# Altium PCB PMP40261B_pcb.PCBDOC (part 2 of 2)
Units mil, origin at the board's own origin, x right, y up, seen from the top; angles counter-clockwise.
Board outline 16142.73 x 9056.12 mil, 2 copper layers (TOP, BOTTOM), stack 10.4 mil thick; 242 components, 121 nets, 575 pads, 103 vias.
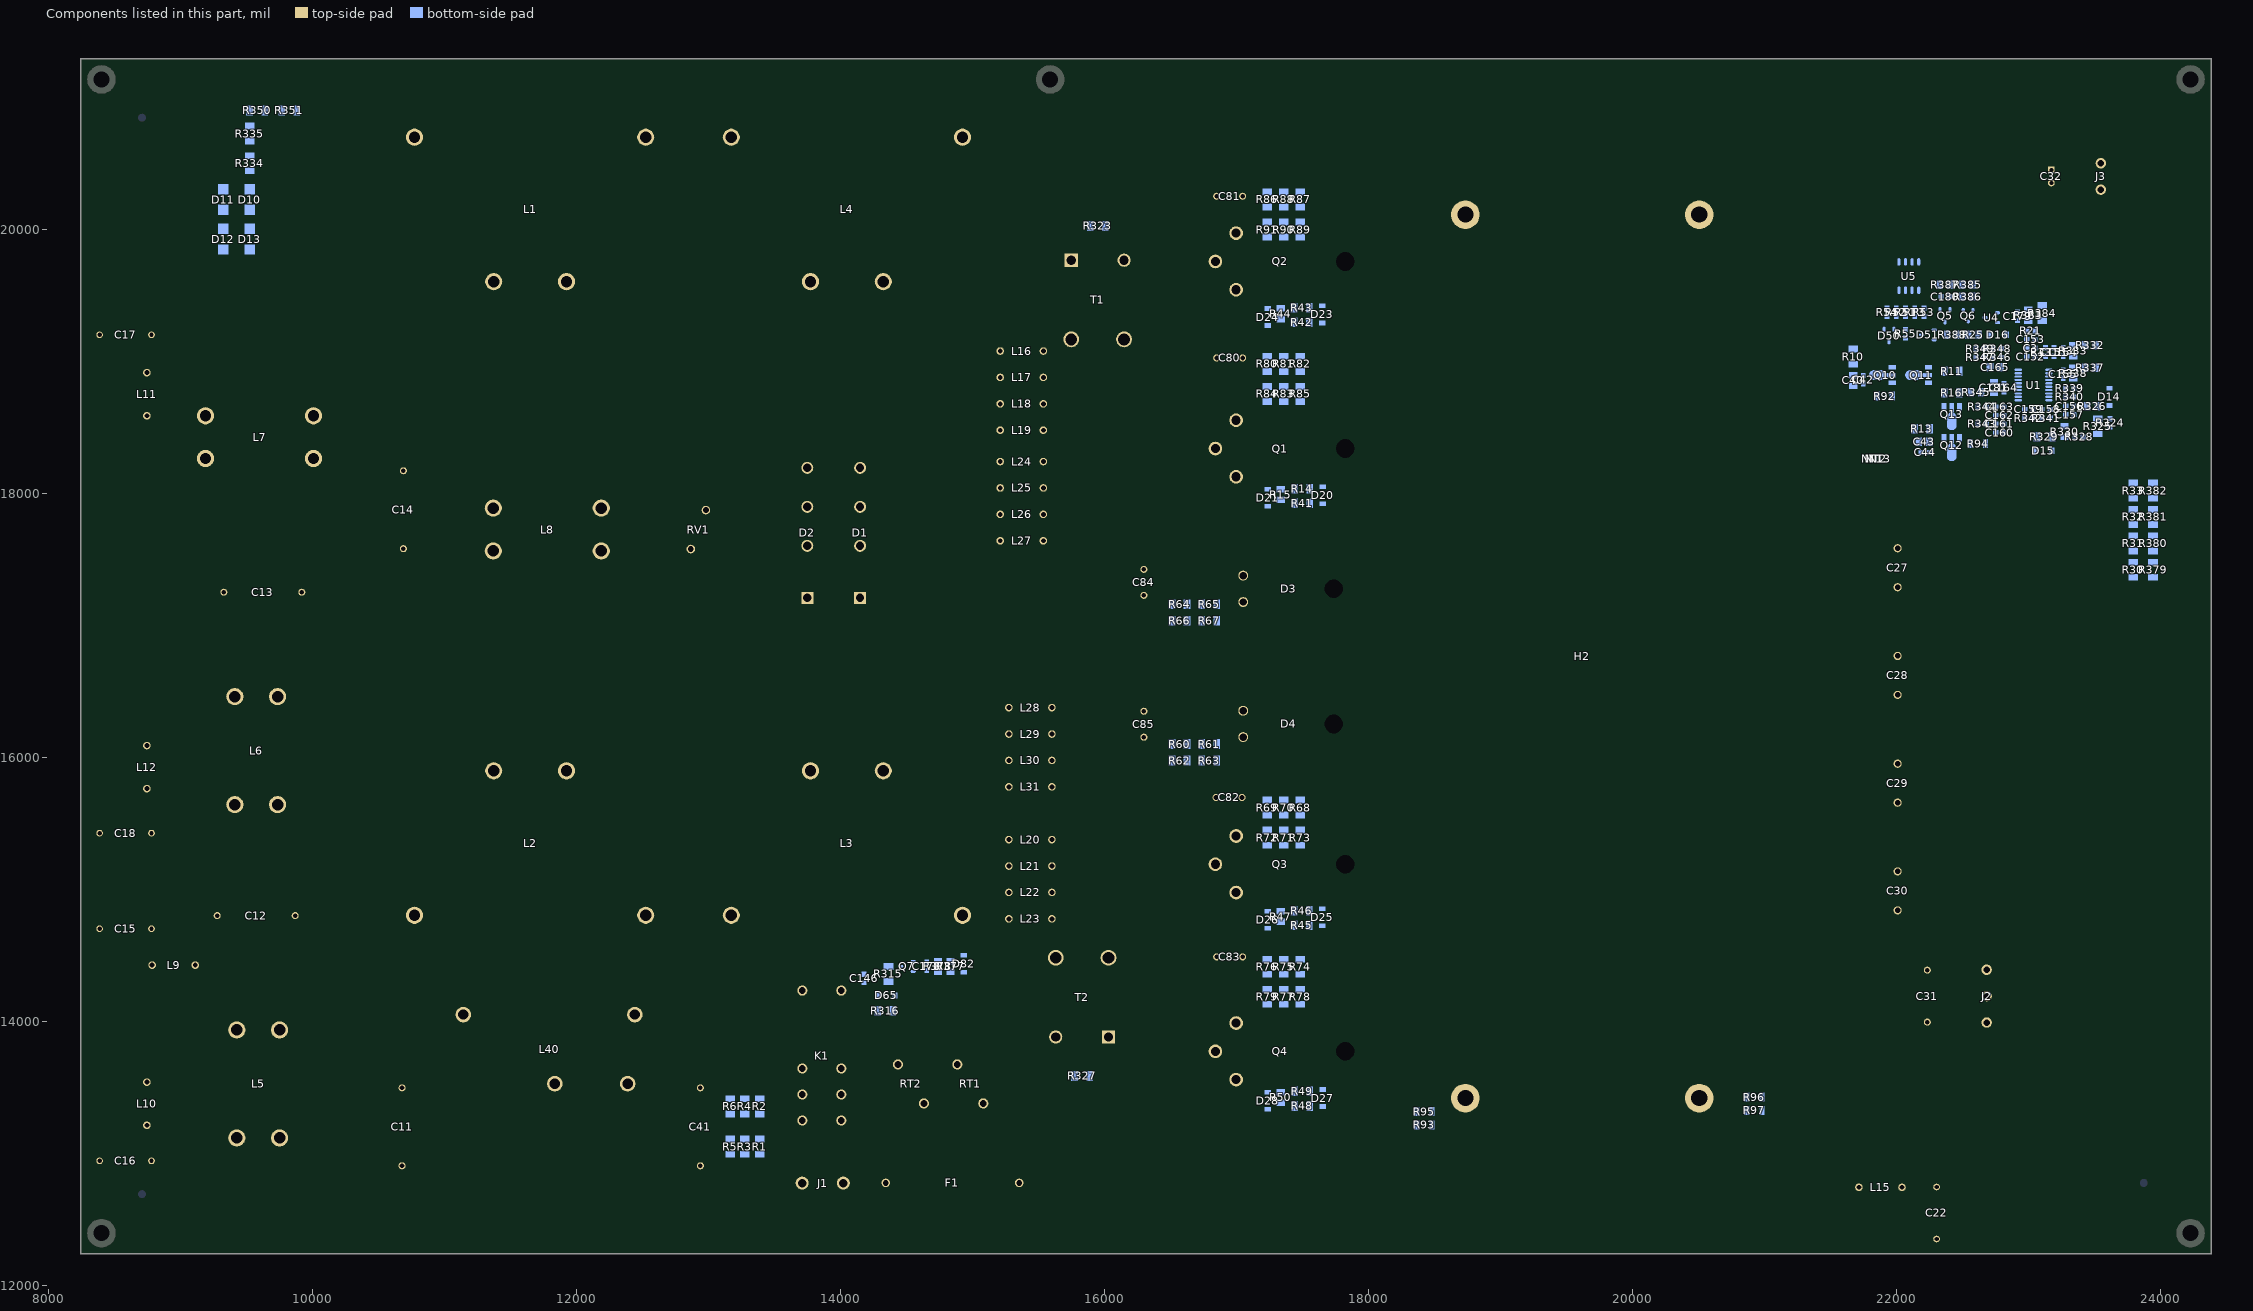
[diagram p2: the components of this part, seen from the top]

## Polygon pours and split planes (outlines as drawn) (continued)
NETR80_2 on BOTTOM "BOTTOM-NETR80_2" (solid, pour order 1054): 17515,18790 17190,18790 17170,18810 17170,18940 17180,18950 17525,18950 17540,18935 17540,18815 17515,18790
NETR74_2 on BOTTOM "BOTTOM-NETR74_2" (solid, pour order 1055): 17515,14223.07 17190,14223.07 17170,14243.07 17170,14373.07 17180,14383.07 17525,14383.07 17540,14368.07 17540,14248.07 17515,14223.07
NETR68_2 on BOTTOM "BOTTOM-NETR68_2" (solid, pour order 1056): 17535,15428.07 17205,15428.07 17190,15443.07 17190,15573.07 17195,15578.07 17535,15578.07 17545,15568.07 17545,15438.07 17535,15428.07
NETR64_1 on BOTTOM "BOTTOM-NETR64_1" (solid, pour order 1057): 16745,16990 16620,16990 16600,17010 16600,17190 16630,17220 16740,17220 16765,17195 16765,17005 16750,16990 16745,16990
NETR60_1 on BOTTOM "BOTTOM-NETR60_1" (solid, pour order 1058): 16745,15930 16620,15930 16600,15950 16600,16130 16630,16160 16740,16160 16765,16135 16765,15945 16750,15930 16745,15930
NETR1_1 on BOTTOM "BOTTOM-NETR1_1" (solid, pour order 1059): 13430,13095 13150,13095 13125,13120 13125,13300 13137.5,13312.5 13437.5,13312.5 13450,13300 13450,13115 13430,13095
NETL20_1 on BOTTOM "BOTTOM-NETL20_1" (solid, pour order 1060): 15550,14425 15525,14450 15525,15350 15525,15440 15560,15475 15715,15475 15725,15475 15795,15475 15825,15445 15825,14460 15790,14425 15735,14425 15550,14425
NETL16_1 on BOTTOM "BOTTOM-NETL16_1" (solid, pour order 1061): 15750,18425 15500,18425 15450,18475 15450,19200 15475,19225 15800,19225 15825,19200 15825,18500 15750,18425
NETL4_2 on BOTTOM "BOTTOM-NETL4_2" (solid, pour order 1062): 17 vertices, not listed, extent 14225,17575 15300,19700
NETL3_1 on BOTTOM "BOTTOM-NETL3_1" (solid, pour order 1063): 20 vertices, not listed, extent 14225,14600 15375,16475
NETL2_1 on BOTTOM "BOTTOM-NETL2_1" (solid, pour order 1064): 11825,15825 11825,15975 11825,16050 11900,16125 13825,16125 13900,16050 13900,15950 13900,15825 13900,15700 13850,15650 11900,15650 11825,15725 11825,15825
NETL1_2 on BOTTOM "BOTTOM-NETL1_2" (solid, pour order 1065): 18 vertices, not listed, extent 11825,19425 13900,20025
NETF1_2 on BOTTOM "BOTTOM-NETF1_2" (solid, pour order 1066): 13950,12700 13950,12825 13950,12875 14000,12925 14375,12925 14425,12875 14425,12825 14425,12700 14425,12650 14375,12600 14000,12600 13950,12650 13950,12700
NETF1_1 on BOTTOM "BOTTOM-NETF1_1" (solid, pour order 1067): 19 vertices, not listed, extent 13650,12675 15500,13425
NETD1_2 on BOTTOM "BOTTOM-NETD1_2" (solid, pour order 1068): 27 vertices, not listed, extent 11100,15625 14225,17650
NETC85_2 on BOTTOM "BOTTOM-NETC85_2" (solid, pour order 1069): 16245,16175 16475,16175 16535,16115 16535,15935 16525,15925 16425,15925 16395,15955 16395,16015 16365,16045 16250,16045 16230,16065 16230,16160 16245,16175
NETC85_1 on BOTTOM "BOTTOM-NETC85_1" (solid, pour order 1070): 22 vertices, not listed, extent 15525,15675 17100,16455
NETC84_2 on BOTTOM "BOTTOM-NETC84_2" (solid, pour order 1071): 16250,17245 16480,17245 16540,17185 16540,17005 16530,16995 16430,16995 16400,17025 16400,17085 16370,17115 16255,17115 16235,17135 16235,17230 16250,17245
NETC84_1 on BOTTOM "BOTTOM-NETC84_1" (solid, pour order 1072): 23 vertices, not listed, extent 15450,17347.5 17100,18300
NETC83_2 on BOTTOM "BOTTOM-NETC83_2" (solid, pour order 1073): 17420,14448.07 17115,14448.07 17090,14423.07 17045,14423.07 17025,14443.07 17025,14538.07 17075,14588.07 17500,14588.07 17525,14588.07 17545,14568.07 17545,14548.07 17545,14463.07 17530,14448.07 17420,14448.07
NETC82_2 on BOTTOM "BOTTOM-NETC82_2" (solid, pour order 1074): 17540,15658.07 17143.07,15658.07 17040,15658.07 17020,15678.07 17020,15743.07 17075,15798.07 17540,15798.07 17550,15788.07 17550,15668.07 17540,15658.07
NETC81_2 on BOTTOM "BOTTOM-NETC81_2" (solid, pour order 1075): 17540,20265 17120,20265 17075,20220 17040,20220 17020,20240 17020,20350 17075,20405 17540,20405 17550,20395 17550,20275 17540,20265
NETC80_2 on BOTTOM "BOTTOM-NETC80_2" (solid, pour order 1076): 17420,19015 17115,19015 17090,18990 17045,18990 17025,19010 17025,19105 17075,19155 17500,19155 17525,19155 17545,19135 17545,19115 17545,19030 17530,19015 17420,19015
NETC80_1 on BOTTOM "BOTTOM-NETC80_1" (solid, pour order 1077): 45 vertices, not listed, extent 16075,18235 16895,20285
NETC41_2 on BOTTOM "BOTTOM-NETC41_2" (solid, pour order 1078): 13480,13400 12350,13400 12275,13475 12275,13700 12350,13775 14925,13775 14950,13750 14950,13650 14950,13600 14925,13575 14525,13575 14362.5,13412.5 13492.5,13412.5 13480,13400
NETC18_1 on BOTTOM "BOTTOM-NETC18_1" (solid, pour order 1079): 20 vertices, not listed, extent 8675.15,15375 8881.57,15800
NETC17_1 on BOTTOM "BOTTOM-NETC17_1" (solid, pour order 1080): 8770.15,19242.15 8750.15,19222.15 8750.15,19032.15 8675,18957 8675,18900 8692.85,18882.15 8702.85,18872.15 8770.15,18872.15 8780.15,18882.15 8790.15,18892.15 8865.15,18967.15 8865.15,19217.15 8860.15,19222.15 8840.15,19242.15 8770.15,19242.15
NETC16_1 on BOTTOM "BOTTOM-NETC16_1" (solid, pour order 1081): 18 vertices, not listed, extent 8715.15,12900 8866.15,13250
NETC15_1 on BOTTOM "BOTTOM-NETC15_1" (solid, pour order 1082): 8775.15,14742.15 8750.15,14717.15 8750.15,14502.15 8750.15,14402.15 8775.15,14377.15 8845.15,14377.15 8865.15,14377.15 8890.15,14402.15 8890.15,14707.15 8855.15,14742.15 8850.15,14742.15 8775.15,14742.15
NETC14_2 on BOTTOM "BOTTOM-NETC14_2" (solid, pour order 1083): 24 vertices, not listed, extent 9900,17250 11450,18325
NETC14_1 on BOTTOM "BOTTOM-NETC14_1" (solid, pour order 1084): 23 vertices, not listed, extent 9925,17825 11475,18950
NETC13_2 on BOTTOM "BOTTOM-NETC13_2" (solid, pour order 1085): 24 vertices, not listed, extent 8660,16025 10200,18350
NETC13_1 on BOTTOM "BOTTOM-NETC13_1" (solid, pour order 1086): 27 vertices, not listed, extent 8575,16350 9500,18725
NETC12_2 on BOTTOM "BOTTOM-NETC12_2" (solid, pour order 1087): 20 vertices, not listed, extent 8675,13475 10200,15725
NETC11_2 on BOTTOM "BOTTOM-NETC11_2" (solid, pour order 1088): 21 vertices, not listed, extent 9675,12925 11950,13750
NETC11_1 on BOTTOM "BOTTOM-NETC11_1" (solid, pour order 1089): 24 vertices, not listed, extent 9225,12550 13775,13225
CASE on BOTTOM "BOTTOM-CASE" (solid, pour order 1090): 78 vertices, not listed, extent 8622,12277.15 24042,12377.15
CASE on BOTTOM "BOTTOM-CASE 1" (solid, pour order 1091): 78 vertices, not listed, extent 8318.3,12590.85 8418.3,20897.15
CASE on BOTTOM "BOTTOM-CASE 2" (solid, pour order 1092): 78 vertices, not listed, extent 8662,21140.85 24022,21240.85
CASE on BOTTOM "BOTTOM-CASE 3" (solid, pour order 1093): 78 vertices, not listed, extent 24228.85,12564 24328.85,20934
no net on Top Overlay (solid): 33 vertices, not listed, extent 23394.06,19382.52 23487.4,19505.37
no net on Top Overlay (solid): 47 vertices, not listed, extent 23505.35,19381.09 23577.87,19505.37
no net on Top Overlay (solid): 23618.11,19441.04 ccw(c23480.05,19441.04) 23480.05,19579.1 ccw(c23480.05,19441.04) 23341.99,19441.04 ccw(c23480.05,19441.04) 23480.05,19302.98 ccw(c23480.05,19441.04) 23618.11,19441.04
no net on Top Overlay (solid): 33 vertices, not listed, extent 23394.06,19382.52 23487.4,19505.37
no net on Top Overlay (solid): 47 vertices, not listed, extent 23505.35,19381.09 23577.87,19505.37
no net on Top Overlay (solid): 23618.11,19441.04 ccw(c23480.05,19441.04) 23480.05,19579.1 ccw(c23480.05,19441.04) 23341.99,19441.04 ccw(c23480.05,19441.04) 23480.05,19302.98 ccw(c23480.05,19441.04) 23618.11,19441.04
no net on PLACE_BOUND_TOP (solid): 15650.4,21134.79 ccw(c15589.4,21134.79) 15589.4,21195.79 ccw(c15589.4,21134.79) 15528.4,21134.79 ccw(c15589.4,21134.79) 15589.4,21073.79 ccw(c15589.4,21134.79) 15650.4,21134.79
no net on PLACE_BOUND_TOP (solid): 15650.4,21134.79 ccw(c15589.4,21134.79) 15589.4,21195.79 ccw(c15589.4,21134.79) 15528.4,21134.79 ccw(c15589.4,21134.79) 15589.4,21073.79 ccw(c15589.4,21134.79) 15650.4,21134.79
no net on PLACE_BOUND_TOP (solid): 24290.4,21134.79 ccw(c24229.4,21134.79) 24229.4,21195.79 ccw(c24229.4,21134.79) 24168.4,21134.79 ccw(c24229.4,21134.79) 24229.4,21073.79 ccw(c24229.4,21134.79) 24290.4,21134.79
no net on PLACE_BOUND_TOP (solid): 24290.4,21134.79 ccw(c24229.4,21134.79) 24229.4,21195.79 ccw(c24229.4,21134.79) 24168.4,21134.79 ccw(c24229.4,21134.79) 24229.4,21073.79 ccw(c24229.4,21134.79) 24290.4,21134.79
no net on PLACE_BOUND_TOP (solid): 8463.63,12394.63 ccw(c8402.63,12394.63) 8402.63,12455.63 ccw(c8402.63,12394.63) 8341.63,12394.63 ccw(c8402.63,12394.63) 8402.63,12333.63 ccw(c8402.63,12394.63) 8463.63,12394.63
no net on PLACE_BOUND_TOP (solid): 8463.63,12394.63 ccw(c8402.63,12394.63) 8402.63,12455.63 ccw(c8402.63,12394.63) 8341.63,12394.63 ccw(c8402.63,12394.63) 8402.63,12333.63 ccw(c8402.63,12394.63) 8463.63,12394.63
no net on PLACE_BOUND_TOP (solid): 24290.4,12394.63 ccw(c24229.4,12394.63) 24229.4,12455.63 ccw(c24229.4,12394.63) 24168.4,12394.63 ccw(c24229.4,12394.63) 24229.4,12333.63 ccw(c24229.4,12394.63) 24290.4,12394.63
no net on PLACE_BOUND_TOP (solid): 24290.4,12394.63 ccw(c24229.4,12394.63) 24229.4,12455.63 ccw(c24229.4,12394.63) 24168.4,12394.63 ccw(c24229.4,12394.63) 24229.4,12333.63 ccw(c24229.4,12394.63) 24290.4,12394.63
no net on PLACE_BOUND_TOP (solid): 8463.63,21134.79 ccw(c8402.63,21134.79) 8402.63,21195.79 ccw(c8402.63,21134.79) 8341.63,21134.79 ccw(c8402.63,21134.79) 8402.63,21073.79 ccw(c8402.63,21134.79) 8463.63,21134.79
no net on PLACE_BOUND_TOP (solid): 8463.63,21134.79 ccw(c8402.63,21134.79) 8402.63,21195.79 ccw(c8402.63,21134.79) 8341.63,21134.79 ccw(c8402.63,21134.79) 8402.63,21073.79 ccw(c8402.63,21134.79) 8463.63,21134.79
no net on PLACE_BOUND_BOTTOM (solid): 8730,12670 8730,12710 8690,12710 8690,12670 8730,12670
no net on PLACE_BOUND_BOTTOM (solid): 23895,12755 23895,12795 23855,12795 23855,12755 23895,12755
no net on PLACE_BOUND_BOTTOM (solid): 8730,20825 8730,20865 8690,20865 8690,20825 8730,20825

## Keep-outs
Multi-Layer:
  circle w1: c17826.06,13771.87 r195
  circle w1: c17826.06,15189.2 r195
  circle w1: c17739.45,16252.19 r195
  circle w1: c17739.45,17275.81 r195
  circle w1: c17826.06,18338.8 r195
  circle w1: c17826.06,19756.13 r195
  region: 16905.15,13950.91 17005.15,13850.91 17005.15,13692.83 16865.18,13552.86 16862.61,13550.51 16859.84,13548.38 16856.9,13546.51 16853.8,13544.9 16850.58,13543.56 16847.25,13542.51 16843.84,13541.76 16840.39,13541.3 16836.9,13541.15 16833.41,13541.3 16829.96,13541.76 16826.55,13542.51 16823.22,13543.56 16820,13544.9 16816.9,13546.51 16813.96,13548.38 16811.19,13550.51 16808.62,13552.86 16806.27,13555.43 16804.14,13558.2 16802.27,13561.15 16800.66,13564.24 16799.32,13567.46 16798.27,13570.79 16797.52,13574.2 16797.06,13577.65 16796.91,13581.14 16797.06,13584.63 16797.52,13588.08 16798.27,13591.49 16799.32,13594.82 16800.66,13598.04 16802.27,13601.14 16804.14,13604.08 16806.27,13606.85 16808.62,13609.42 16925.15,13725.95 16925.15,13817.79 16825.15,13917.79 16825.15,14057.89 16825.3,14061.38 16825.76,14064.84 16826.51,14068.24 16827.56,14071.57 16828.9,14074.79 16830.51,14077.89 16832.38,14080.83 16834.51,14083.6 16836.87,14086.17 16839.44,14088.53 16842.21,14090.66 16845.15,14092.53 16848.25,14094.14 16851.47,14095.48 16854.8,14096.53 16858.2,14097.28 16861.66,14097.74 16865.15,14097.89 16868.64,14097.74 16872.1,14097.28 16875.5,14096.53 16878.83,14095.48 16882.05,14094.14 16885.15,14092.53 16888.09,14090.66 16890.86,14088.53 16893.43,14086.17 16895.79,14083.6 16897.92,14080.83 16899.79,14077.89 16901.4,14074.79 16902.74,14071.57 16903.79,14068.24 16904.54,14064.84 16905,14061.38 16905.15,14057.89 16905.15,13950.91
  region: 16905.15,15368.24 17005.15,15268.24 17005.15,15110.16 16865.18,14970.19 16862.61,14967.84 16859.84,14965.71 16856.9,14963.84 16853.8,14962.23 16850.58,14960.89 16847.25,14959.84 16843.84,14959.09 16840.39,14958.63 16836.9,14958.48 16833.41,14958.63 16829.96,14959.09 16826.55,14959.84 16823.22,14960.89 16820,14962.23 16816.9,14963.84 16813.96,14965.71 16811.19,14967.84 16808.62,14970.19 16806.27,14972.76 16804.14,14975.53 16802.27,14978.48 16800.66,14981.57 16799.32,14984.79 16798.27,14988.12 16797.52,14991.53 16797.06,14994.98 16796.91,14998.47 16797.06,15001.96 16797.52,15005.41 16798.27,15008.82 16799.32,15012.15 16800.66,15015.37 16802.27,15018.47 16804.14,15021.41 16806.27,15024.18 16808.62,15026.75 16925.15,15143.28 16925.15,15235.12 16825.15,15335.12 16825.15,15475.22 16825.3,15478.71 16825.76,15482.17 16826.51,15485.57 16827.56,15488.9 16828.9,15492.12 16830.51,15495.22 16832.38,15498.16 16834.51,15500.93 16836.87,15503.5 16839.44,15505.86 16842.21,15507.99 16845.15,15509.86 16848.25,15511.47 16851.47,15512.81 16854.8,15513.86 16858.2,15514.61 16861.66,15515.07 16865.15,15515.22 16868.64,15515.07 16872.1,15514.61 16875.5,15513.86 16878.83,15512.81 16882.05,15511.47 16885.15,15509.86 16888.09,15507.99 16890.86,15505.86 16893.43,15503.5 16895.79,15500.93 16897.92,15498.16 16899.79,15495.22 16901.4,15492.12 16902.74,15488.9 16903.79,15485.57 16904.54,15482.17 16905,15478.71 16905.15,15475.22 16905.15,15368.24
  region: 16905.15,18517.84 17005.15,18417.84 17005.15,18259.76 16865.18,18119.79 16862.61,18117.44 16859.84,18115.31 16856.9,18113.44 16853.8,18111.83 16850.58,18110.49 16847.25,18109.44 16843.84,18108.69 16840.39,18108.23 16836.9,18108.08 16833.41,18108.23 16829.96,18108.69 16826.55,18109.44 16823.22,18110.49 16820,18111.83 16816.9,18113.44 16813.96,18115.31 16811.19,18117.44 16808.62,18119.79 16806.27,18122.36 16804.14,18125.13 16802.27,18128.08 16800.66,18131.17 16799.32,18134.39 16798.27,18137.72 16797.52,18141.13 16797.06,18144.58 16796.91,18148.07 16797.06,18151.56 16797.52,18155.01 16798.27,18158.42 16799.32,18161.75 16800.66,18164.97 16802.27,18168.06 16804.14,18171.01 16806.27,18173.78 16808.62,18176.35 16925.15,18292.88 16925.15,18384.72 16825.15,18484.72 16825.15,18624.82 16825.3,18628.31 16825.76,18631.77 16826.51,18635.17 16827.56,18638.5 16828.9,18641.72 16830.51,18644.82 16832.38,18647.76 16834.51,18650.53 16836.87,18653.1 16839.44,18655.46 16842.21,18657.59 16845.15,18659.46 16848.25,18661.07 16851.47,18662.41 16854.8,18663.46 16858.2,18664.21 16861.66,18664.67 16865.15,18664.82 16868.64,18664.67 16872.1,18664.21 16875.5,18663.46 16878.83,18662.41 16882.05,18661.07 16885.15,18659.46 16888.09,18657.59 16890.86,18655.46 16893.43,18653.1 16895.79,18650.53 16897.92,18647.76 16899.79,18644.82 16901.4,18641.72 16902.74,18638.5 16903.79,18635.17 16904.54,18631.77 16905,18628.31 16905.15,18624.82 16905.15,18517.84
  region: 16905.15,19935.17 17005.15,19835.17 17005.15,19677.09 16865.18,19537.12 16862.61,19534.77 16859.84,19532.64 16856.9,19530.77 16853.8,19529.16 16850.58,19527.82 16847.25,19526.77 16843.84,19526.02 16840.39,19525.56 16836.9,19525.41 16833.41,19525.56 16829.96,19526.02 16826.55,19526.77 16823.22,19527.82 16820,19529.16 16816.9,19530.77 16813.96,19532.64 16811.19,19534.77 16808.62,19537.12 16806.27,19539.69 16804.14,19542.46 16802.27,19545.4 16800.66,19548.5 16799.32,19551.72 16798.27,19555.05 16797.52,19558.46 16797.06,19561.91 16796.91,19565.4 16797.06,19568.89 16797.52,19572.34 16798.27,19575.75 16799.32,19579.08 16800.66,19582.3 16802.27,19585.4 16804.14,19588.34 16806.27,19591.11 16808.62,19593.68 16925.15,19710.21 16925.15,19802.05 16825.15,19902.05 16825.15,20042.15 16825.3,20045.64 16825.76,20049.1 16826.51,20052.5 16827.56,20055.83 16828.9,20059.05 16830.51,20062.15 16832.38,20065.09 16834.51,20067.86 16836.87,20070.43 16839.44,20072.79 16842.21,20074.92 16845.15,20076.79 16848.25,20078.4 16851.47,20079.74 16854.8,20080.79 16858.2,20081.54 16861.66,20082 16865.15,20082.15 16868.64,20082 16872.1,20081.54 16875.5,20080.79 16878.83,20079.74 16882.05,20078.4 16885.15,20076.79 16888.09,20074.92 16890.86,20072.79 16893.43,20070.43 16895.79,20067.86 16897.92,20065.09 16899.79,20062.15 16901.4,20059.05 16902.74,20055.83 16903.79,20052.5 16904.54,20049.1 16905,20045.64 16905.15,20042.15 16905.15,19935.17

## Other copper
TOP:
  pour cut-out: 258 vertices and 0 holes, not listed, extent 17631.03,13576.84 18021.09,13966.9
  pour cut-out: 258 vertices and 0 holes, not listed, extent 17631.03,14994.17 18021.09,15384.23
  pour cut-out: 258 vertices and 0 holes, not listed, extent 17544.42,16057.16 17934.48,16447.22
  pour cut-out: 258 vertices and 0 holes, not listed, extent 17544.42,17080.78 17934.48,17470.84
  pour cut-out: 258 vertices and 0 holes, not listed, extent 17631.03,18143.77 18021.09,18533.83
  pour cut-out: 258 vertices and 0 holes, not listed, extent 17631.03,19561.1 18021.09,19951.16
Multi-Layer:
  lines w1: 8265.15,12257.15 24366.88,12257.15 24366.88,21272.27 8265.15,21272.27 8265.15,12257.15 ; 8555.15,12547.15 24076.88,12547.15 24076.88,20982.27 8555.15,20982.27 8555.15,12547.15

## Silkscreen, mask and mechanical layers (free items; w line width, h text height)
Top Overlay:
  drawing of 302 lines, arcs and shapes, not listed
  text "8" at 6202.6,27865 h156
  text "8" at 6202.6,27865 h156
  text "7" at 10327.6,27865 h156
  text "7" at 10327.6,27865 h156
  text "6" at 14452.6,27865 h156
  text "6" at 14452.6,27865 h156
  text "5" at 18577.6,27865 h156
  text "5" at 18577.6,27865 h156
  text "4" at 22702.6,27865 h156
  text "4" at 22702.6,27865 h156
  text "3" at 26827.6,27865 h156
  text "3" at 26827.6,27865 h156
  text "2" at 30952.6,27865 h156
  text "2" at 30952.6,27865 h156
  text "1" at 35077.6,27865 h156
  text "1" at 35077.6,27865 h156
  text "D" at 3987.6,25065 h156
  text "D" at 3987.6,25065 h156
  text "D" at 37300,25065 h125
  text "D" at 37300,25065 h125
  text "DEV/SILKSCREEN" at 8130.26,21430.07 h17
  text "DEV/SILKSCREEN" at 15317.03,21430.07 h17
  text "DEV/SILKSCREEN" at 23957.03,21430.07 h17
  text "VAL/SILKSCREEN" at 8130.26,21390.7 h17
  text "VAL/SILKSCREEN" at 15317.03,21390.7 h17
  text "VAL/SILKSCREEN" at 23957.03,21390.7 h17
  text "PMP40261_REVB" at 8875,20500 h100
  text "C" at 3987.6,19815 h156
  text "C" at 3987.6,19815 h156
  text "C" at 37300,19815 h125
  text "C" at 37300,19815 h125
  text "B" at 3987.6,14565 h156
  text "B" at 3987.6,14565 h156
  text "B" at 37300,14565 h125
  text "B" at 37300,14565 h125
  text "DEV/SILKSCREEN" at 8130.26,12689.91 h17
  text "DEV/SILKSCREEN" at 23957.03,12689.91 h17
  text "VAL/SILKSCREEN" at 8130.26,12650.54 h17
  text "VAL/SILKSCREEN" at 23957.03,12650.54 h17
  text "A" at 37300,9315 h125
  text "A" at 37300,9315 h125
  text "8" at 6202.6,6510 h156
  text "8" at 6202.6,6510 h156
  text "7" at 10327.6,6510 h156
  text "7" at 10327.6,6510 h156
  text "6" at 14452.6,6510 h156
  text "6" at 14452.6,6510 h156
  text "5" at 18577.6,6510 h156
  text "5" at 18577.6,6510 h156
  text "4" at 22702.6,6510 h156
  text "4" at 22702.6,6510 h156
  text "3" at 26827.6,6510 h156
  text "3" at 26827.6,6510 h156
  text "2" at 30952.6,6510 h156
  text "2" at 30952.6,6510 h156
  text "1" at 35077.6,6510 h156
  text "1" at 35077.6,6510 h156
Bottom Overlay:
  lines w5: 3700,6265 3700,28265 ; 3700,6265 37700,6265 ; 3700,6265 3700,28265 ; 3700,6265 37700,6265 ; 3700,28265 37700,28265 ; 3700,28265 37700,28265 ; 37700,6265 37700,28265 ; 37700,6265 37700,28265
  lines w6: 22515,18935 22550,18935 ; 22790,19245 22820,19275 ; 23130.15,18227.15 23130.15,18262.15 ; 23295.15,18982.15 22850.15,18982.15 22850.15,18997.15 22665.15,18997.15 22665.15,18887.15 22690.15,18887.15 22690.15,18697.15 22715.15,18697.15 22715.15,18262.15 23460.15,18262.15 23460.15,18482.15 23390.15,18482.15 23390.15,18982.15 23385.15,18982.15 ; 22550,18935 22545,18940 22545,18930 22550,18935 ; 22820,19275 22810,19275 22820,19265 22820,19275 ; 23390,19165 23390,19190 ; 23390,19165 23390,19010 23390,18990 22945,18990 22945,19260 23105,19260 23105,19165 23390,19165 ; 23390,19190 23620,19190 23620,19360 23395,19360 23395,19445 23185,19445 23185,19190 23390,19190 ; 22720,17650 22720,18225 23485,18225 23530,18225 23530,17650 22720,17650
  lines w20: 4000,17165 4000,17365 ; 4000,17165 4200,17265 ; 4000,17165 4000,17365 ; 4000,17165 4200,17265 ; 4000,17365 4200,17265 ; 4000,17365 4200,17265 ; 4200,6765 4200,27765 ; 4200,6765 37200,6765 ; 4200,6765 4200,27765 ; 4200,6765 37200,6765 ; 4200,17265 3800,17265 4200,17265 ; 4200,27765 37200,27765 ; 4200,27765 37200,27765 ; 20600,6565 20700,6765 ; 20600,6565 20800,6565 ; 20600,6565 20700,6765 ; 20600,6565 20800,6565 ; 20600,27965 20700,27765 ; 20600,27965 20800,27965 ; 20600,27965 20700,27765 ; 20600,27965 20800,27965 ; 20700,6765 20700,6365 20700,6765 ; 20700,6765 20800,6565 ; 20700,6765 20800,6565 ; 20700,27765 20700,28165 20700,27765 ; 20700,27765 20800,27965 ; 20700,27765 20800,27965 ; 37200,6765 37200,27765 ; 37200,6765 37200,27765 ; 37200,17265 37400,17165 ; 37200,17265 37400,17365 ; 37200,17265 37600,17265 37200,17265 ; 37200,17265 37400,17165 ; 37200,17265 37400,17365 ; 37400,17165 37400,17365 ; 37400,17165 37400,17365 ; 3800,22515 4200,22515 3800,22515 ; 8325,6365 8325,6765 8325,6365 ; 8325,27765 8325,28165 8325,27765 ; 12450,6365 12450,6765 12450,6365 ; 12450,27765 12450,28165 12450,27765 ; 16575,6365 16575,6765 16575,6365 ; 16575,27765 16575,28165 16575,27765 ; 24825,6365 24825,6765 24825,6365 ; 24825,27765 24825,28165 24825,27765 ; 28950,6365 28950,6765 28950,6365 ; 28950,27765 28950,28165 28950,27765 ; 33075,6365 33075,6765 33075,6365 ; 33075,27765 33075,28165 33075,27765 ; 37200,12015 37600,12015 37200,12015 ; 37200,22515 37600,22515 37200,22515
  text "8" at 6202.6,27865 h156
  text "8" at 6202.6,27865 h156
  text "7" at 10327.6,27865 h156
  text "7" at 10327.6,27865 h156
  text "6" at 14452.6,27865 h156
  text "6" at 14452.6,27865 h156
  text "5" at 18577.6,27865 h156
  text "5" at 18577.6,27865 h156
  text "4" at 22702.6,27865 h156
  text "4" at 22702.6,27865 h156
  text "3" at 26827.6,27865 h156
  text "3" at 26827.6,27865 h156
  text "2" at 30952.6,27865 h156
  text "2" at 30952.6,27865 h156
  text "1" at 35077.6,27865 h156
  text "1" at 35077.6,27865 h156
  text "D" at 3987.6,25065 h156
  text "D" at 3987.6,25065 h156
  text "D" at 37300,25065 h125
  text "D" at 37300,25065 h125
  text "DEV" at 8785,21045 h51
  text "ID3" at 8760,20720 h35
  text "C" at 3987.6,19815 h156
  text "C" at 3987.6,19815 h156
  text "C" at 37300,19815 h125
  text "C" at 37300,19815 h125
  text "B" at 3987.6,14565 h156
  text "B" at 3987.6,14565 h156
  text "B" at 37300,14565 h125
  text "B" at 37300,14565 h125
  text "DEV" at 23950,12975 h51
  text "DEV" at 8785,12890 h51
  text "ID2" at 23925,12850 h35
  text "ID1" at 8760,12780 h35
  text "A" at 37300,9315 h125
  text "A" at 37300,9315 h125
  text "8" at 6202.6,6510 h156
  text "8" at 6202.6,6510 h156
  text "7" at 10327.6,6510 h156
  text "7" at 10327.6,6510 h156
  text "6" at 14452.6,6510 h156
  text "6" at 14452.6,6510 h156
  text "5" at 18577.6,6510 h156
  text "5" at 18577.6,6510 h156
  text "4" at 22702.6,6510 h156
  text "4" at 22702.6,6510 h156
  text "3" at 26827.6,6510 h156
  text "3" at 26827.6,6510 h156
  text "2" at 30952.6,6510 h156
  text "2" at 30952.6,6510 h156
  text "1" at 35077.6,6510 h156
  text "1" at 35077.6,6510 h156
NCLEGEND-1-2:
  circle w1: c27199.5,11698.5 r27.56
  lines w1: 26750,9310 31586,9310 ; 26750,9591 31586,9591 ; 26750,9872 31586,9872 ; 26750,10153 31586,10153 ; 26750,10434 31586,10434 ; 26750,10715 31586,10715 ; 26750,10996 31586,10996 ; 26750,11277 31586,11277 ; 26750,11558 31586,11558 ; 26750,11839 31586,11839 ; 26750,12120 31586,12120 ; 26750,12401 31586,12401 ; 26750,12682 31586,12682 ; 26750,12963 31586,12963 ; 26750,13244 31586,13244 ; 26750,13525 31586,13525 ; 26750,13806 31586,13806 ; 26750,14087 31586,14087 ; 26750,14368 31586,14368 ; 26750,14649 31586,14649 ; 26750,14930 31586,14930 ; 27191.5,14227.5 27207.5,14227.5 ; 27199.5,14219.5 27199.5,14235.5 ; 27649,9029 27649,14649 ; 29540,9029 29540,14649 ; 30811,9029 30811,14649 ; 26750,9029 31586,9029 31586,15180 26750,15180 26750,9029 ; 27159.02,13103.5 27170.88,13132.12 27199.5,13143.98 27228.12,13132.12 27239.98,13103.5 27228.12,13074.88 27199.5,13063.02 27170.88,13074.88 27159.02,13103.5 ; 27162.59,12254.35 ccw(c27199.5,12254.35) 27236.41,12254.35 27236.41,12266.65 ccw(c27199.5,12266.65) 27162.59,12266.65 27162.59,12254.35 ; 27173.91,11960.31 27225.09,11960.31 27225.09,11998.69 27173.91,11998.69 27173.91,11960.31 ; 27178.83,12822.5 27199.5,12801.83 27220.17,12822.5 27199.5,12843.17 27178.83,12822.5 ; 27181.78,13375.64 27181.78,13393.36 27199.5,13402.22 27217.22,13393.36 27217.22,13375.64 27199.5,13366.78 27181.78,13375.64 ; 27182.77,13665.5 27191.13,13682.23 27207.87,13682.23 27216.23,13665.5 27207.87,13648.77 27191.13,13648.77 27182.77,13665.5 ; 27183.75,13930.75 27183.75,13962.25 27215.25,13962.25 27215.25,13930.75 27183.75,13930.75 ; 27199.5,12498.19 ccw(c27199.5,12541.5) 27199.5,12584.81 ccw(c27199.5,12541.5) 27199.5,12498.19
  text "DRILL CHART: TOP to BOTTOM" at 27868,14992.5 h125
  text "ALL UNITS ARE IN MILS" at 28118,14742.5 h125
  text "FIGURE" at 26899.5,14461.5 h125
  text "SIZE" at 28394.5,14461.5 h125
  text "PLATED" at 29875.5,14461.5 h125
  text "QTY" at 31048.5,14461.5 h125
  text "16.0" at 28394.5,14165 h125
  text "PLATED" at 29875.5,14165 h125
  text "103" at 31048.5,14165 h125
  text "31.5" at 28394.5,13884 h125
  text "PLATED" at 29875.5,13884 h125
  text "2" at 31148.5,13884 h125
  text "33.46" at 28344.5,13603 h125
  text "PLATED" at 29875.5,13603 h125
  text "12" at 31098.5,13603 h125
  text "35.43" at 28344.5,13322 h125
  text "PLATED" at 29875.5,13322 h125
  text "22" at 31098.5,13322 h125
  text "37.4" at 28394.5,13041 h125
  text "PLATED" at 29875.5,13041 h125
  text "42" at 31098.5,13041 h125
  text "41.34" at 28344.5,12760 h125
  text "PLATED" at 29875.5,12760 h125
  text "8" at 31148.5,12760 h125
  text "43.31" at 28344.5,12479 h125
  text "PLATED" at 29875.5,12479 h125
  text "4" at 31148.5,12479 h125
  text "49.21" at 28344.5,12198 h125
  text "PLATED" at 29875.5,12198 h125
  text "5" at 31148.5,12198 h125
  text "51.18" at 28344.5,11917 h125
  text "PLATED" at 29875.5,11917 h125
  text "12" at 31098.5,11917 h125
  text "55.12" at 28344.5,11636 h125
  text "PLATED" at 29875.5,11636 h125
  text "4" at 31148.5,11636 h125
  text "62.99" at 28344.5,11355 h125
  text "PLATED" at 29875.5,11355 h125
  text "8" at 31148.5,11355 h125
  text "64.96" at 28344.5,11074 h125
  text "PLATED" at 29875.5,11074 h125
  text "2" at 31148.5,11074 h125
  text "68.9" at 28394.5,10793 h125
  text "PLATED" at 29875.5,10793 h125
  text "12" at 31098.5,10793 h125
  text "70.0" at 28394.5,10512 h125
  text "PLATED" at 29875.5,10512 h125
  text "4" at 31148.5,10512 h125
  text "78.74" at 28344.5,10231 h125
  text "PLATED" at 29875.5,10231 h125
  text "4" at 31148.5,10231 h125
  text "86.61" at 28344.5,9950 h125
  text "PLATED" at 29875.5,9950 h125
  text "32" at 31098.5,9950 h125
  text "89.0" at 28394.5,9669 h125
  text "PLATED" at 29875.5,9669 h125
  text "4" at 31148.5,9669 h125
  text "122.05" at 28294.5,9388 h125
  text "PLATED" at 29875.5,9388 h125
  text "9" at 31148.5,9388 h125
  text "141.73" at 28294.5,9107 h125
  text "NON-PLATED" at 29675.5,9107 h125
  text "6" at 31148.5,9107 h125
REFDES BOTTOM DRC:
  lines w1: 21600,19370 21930,19370 ; 21660,19370 22000,19370 ; 21720,19370 22070,19370 ; 21780,19370 22140,19370 ; 21840,19370 22210,19370 ; 22370,19490 22370,19640 ; 22370,19580 22370,19705 ; 22540,19490 22540,19645 ; 22540,19580 22540,19705 ; 22750,18955 22820,18150 ; 22785,18590 22820,17860 ; 22785,18655 22820,17915 ; 23115,18335 23185,17690 ; 23125,18440 23175,17750
REFDES TOP DRC:
  lines w1: 8550,12950 8660,12735 ; 8550,14700 8665,14895 ; 8550,15425 8660,15610 ; 8550,19200 8655,18980 ; 8625,13400 8746.85,13375 ; 8625,15925 8746.85,15925 ; 8625,18750 8746.85,18750 ; 8950,14425 8950,14550 ; 9575,14275 9590,13525 ; 9575,14800 9575,15025 ; 9575,16050 9575,16825 ; 9600,18425 9600,19175 ; 9625,17250 9625,17475 ; 10680,13200 10700,13700 ; 10690,17875 10700,17375 ; 11650,15350 11650,16800 ; 11650,20150 11675,20925 ; 11775,18475 11780,17725 ; 11800,13525 11800,14325 ; 12925,17725 12925,18150 ; 12940,13200 12950,13700 ; 13750,17700 13750,18400 ; 13850,13000 13866.99,12774 ; 13860,13740 13875,14375 ; 14025,16800 14050,15350 ; 14050,20150 14075,20950 ; 14125,18400 14150,17700 ; 14535,13525 14550,14075 ; 14825,12925 14850,12775 ; 14985,13525 15000,14075 ; 15375,17640 15696.73,17626.25 ; 15375,17840 15696.73,17826.25 ; 15375,18040 15696.73,18026.25 ; 15375,18240 15696.73,18226.25 ; 15375,18477.26 15696.73,18463.51 ; 15375,18677.26 15696.73,18663.51 ; 15375,18877.26 15696.73,18863.51 ; 15375,19077.26 15375,19200 ; 15440,14775.74 15761.73,14761.99 ; 15440,14975.74 15761.73,14961.99 ; 15440,15175.74 15761.73,15161.99 ; 15440,15375.74 15761.73,15361.99 ; 15440,15775.74 15761.73,15761.99 ; 15440,15975.74 15761.73,15961.99 ; 15440,16175.74 15761.73,16161.99 ; 15440,16375.74 15761.73,16361.99 ; 15825,14600 15831.89,14180.54 ; 15950,19465.57 15950,19900 ; 16150,17325 16300,17325 ; 16300,16250 16500,16250 ; 16675,15183.07 16841.81,15189.2 ; 16675,18316.93 16841.81,18338.8 ; 16675,19742.52 16841.81,19756.13 ; 16700,13757.48 16841.81,13771.87 ; 16825,17278.15 17052.44,17275.81 ; 16850,16246.85 17052.44,16252.19 ; 16945,15695 16945,15845 ; 16950,14487.52 16950,14620 ; 16950,19025 16950,19175 ; 16950,20250 16950,20400 ; 19404.8,16764 19550,20775 ; 21665,12645 21850,12525 ; 21850,13300 22025,13300 ; 21875,15825 22009.8,15803.3 ; 21875,16625 22009.8,16619.5 ; 21875,17450 22009.8,17435.7 ; 21900,15000 22009.8,14987.1 ; 22050,14200 22235,14190 ; 22685,14190 22975,14150 ; 23000,20400 23175,20400 ; 23550,20400 23825,20375
DIMENSION:
  drawing of 44659 lines, arcs and shapes, not listed
  text "8" at 6202.6,27865 h156
  text "8" at 6202.6,27865 h156
  text "7" at 10327.6,27865 h156
  text "7" at 10327.6,27865 h156
  text "6" at 14452.6,27865 h156
  text "6" at 14452.6,27865 h156
  text "5" at 18577.6,27865 h156
  text "5" at 18577.6,27865 h156
  text "4" at 22702.6,27865 h156
  text "4" at 22702.6,27865 h156
  text "3" at 26827.6,27865 h156
  text "3" at 26827.6,27865 h156
  text "2" at 30952.6,27865 h156
  text "2" at 30952.6,27865 h156
  text "1" at 35077.6,27865 h156
  text "1" at 35077.6,27865 h156
  text "D" at 3987.6,25065 h156
  text "D" at 3987.6,25065 h156
  text "D" at 37300,25065 h125
  text "D" at 37300,25065 h125
  text "Fab Drawing Notes" at 29949.48,22321.94 h80
  text "410.00(MM)" at 15716.01,21892.27 h150
  text "BOARD NAME:  PMP40261B" at 26849.48,21871.94 h80
  text "BOARD LAYER:  2" at 30649.48,21871.94 h80
  text "BOARD SIZE:  410 X 230 MM(+/-10%)" at 26849.48,21671.94 h80
  text "BOARD THICKNESS: 2  MM(+/-10%)" at 30649.48,21671.94 h80
  text "16141.73(Mils)" at 15476.01,21542.27 h150
  text "SOLDER MASK: IPC SM-840" at 26849.48,21471.94 h80
  text "SILKSCREEN LAYER: TOP && BOTTOM" at 30649.48,21471.94 h80
  text "CONTROL IMPEDANCE: NO" at 26849.48,21271.94 h80
  text "IMPEDANCE REPORT: NO" at 30649.48,21271.94 h80
  text "SOLDER COLORS:    GREEN            RED         YELLOW           BLACK         OTHER" at 26849.48,21071.94 h80
  text "SILKSCREEN COLORS:WHITE            RED         YELLOW           BLACK         OTHER" at 26849.48,20871.94 h80
  text "SURFACE FINISHED:HASL(Sn/Pb)            HASL(Pb-Free)            ELECTROLYTIC GOLD" at 26849.48,20671.94 h80
  text "ENIG                      OSP                         OTHER" at 26849.48,20471.94 h80
  text "BOARD MATERIAL:         FR-4               FR-4 TG150                    FR-4 TG170" at 26849.48,20271.94 h80
  text "ROGERS 4003             ROGERS 4350B                         OTHER" at 26849.48,20071.94 h80
  text "VIA TECHNIC:  ALL VIA FILLED                BY GERBER                         OTHER" at 26849.48,19871.94 h80
  text "C" at 3987.6,19815 h156
  text "C" at 3987.6,19815 h156
  text "C" at 37300,19815 h125
  text "C" at 37300,19815 h125
  text "INSPECTION STANDARD:  IPC-II      IPC-III         GJB         GB-4588         OTHER" at 26849.48,19671.94 h80
  text "BOW & TWIST TOLERANCE: <=0.75%    HOLES(TOL):+/-0.0762mm   PRESS FIT HOLES(TOL):+/-0.05mm" at 26849.48,19471.94 h80
  text "OPEN WINDOWS: YES                 SPELL MODE:1:1" at 26849.48,19271.94 h80
  text "DATE: 2017-12-07" at 26849.48,19071.94 h80
  text "DESIGNER: wud" at 29569.48,19071.94 h80
  text "DESIGNER: wud@kingbrother.com" at 31569.48,19071.94 h80
  text "NETLIST REPORT:" at 29695,18880 h80
  text "OTHER:" at 26849.48,18871.94 h80
  text "V-cut Detail:" at 31099.48,18871.94 h80
  text "1.SHORTED (XX)" at 29695,18755 h63
  text "1.OBLONG VIAS:[NO]" at 26845,18730 h80
  text "2.BROKEN (XX)" at 29695,18630 h63
  text "2.PRESS FIT HOLES:[NO]" at 26849.48,18571.94 h80
  text "T" at 31949.48,18561.94 h80
  text "1/3T" at 33249.48,18561.94 h80
  text "3.MISSING (XX)" at 29695,18505 h63
  text "3.xxxxx" at 26849.48,18421.94 h80
  text "4.EXTRA (XX)" at 29695,18380 h63
  text "Angle<45" at 33099.48,18371.94 h80
  text "For Flash D-Code" at 26745,17980 h80
  text "45" at 30870,17655 h80
  text "D" at 30845,17205 h80
  text "ID" at 30345,17180 h80
  text "w" at 29820,17030 h80
  text "OD" at 30345,17005 h80
  text "9055.12(Mils)" at 23956.88,16764.71 h150 r90
  text "230.00(MM)" at 24536.88,16764.71 h150 r90
  text "For example :  FLASH 50 0 D33" at 26695,16605 h80
  text "FLASH:The D code shape is THERMAL" at 26695,16455 h80
  text "50:Recommended Thermal pad's OD(out-diamter)is 50mil" at 26695,16305 h80
  text "0:It means as angle,but we can ignore it here,The priority Thermal angle is 45" at 26695,16180 h80
  text "D33:Flaged the D code" at 26695,16030 h80
  text "(Thermal pad's angle,W,ID depends on the ability of the factory,they'll adjusted the paramete)" at 26695,15880 h80
  text "Note:If OD not bigger than D,then The D code will full connected this hole." at 26720,15730 h80
  text "(Some of the via used this method)" at 26720,15580 h80
  text "B" at 3987.6,14565 h156
  text "B" at 3987.6,14565 h156
  text "B" at 37300,14565 h125
  text "B" at 37300,14565 h125
  text "A" at 3987.6,9315 h156
  text "A" at 3987.6,9315 h156
  text "A" at 37300,9315 h125
  text "A" at 37300,9315 h125
  text "SIZE:A1" at 30250,7900 h90
  text "SIZE:A1" at 30250,7900 h90
  text "Part No:" at 31733.2,7825 h90
  text "Part No:" at 31733.2,7825 h90
  text "Revision:" at 32858.2,7825 h90
  text "Revision:" at 32858.2,7825 h90
  text "Data:" at 33958.2,7825 h90
  text "Data:" at 33958.2,7825 h90
  text "Designer:" at 34908.2,7825 h90
  text "Designer:" at 34908.2,7825 h90
  text "QA:" at 36058.2,7825 h90
  text "QA:" at 36058.2,7825 h90
  text "DIMENSIONS:INCHES" at 30250,7700 h90
  text "DIMENSIONS:INCHES" at 30250,7700 h90
  text "D2017110102" at 31750,7625 h90
  text "D2017110102" at 31750,7625 h90
  text "1.0" at 33133.2,7625 h90
  text "1.0" at 33133.2,7625 h90
  text "2017-12-07" at 33958.2,7625 h90
  text "2017-12-07" at 33958.2,7625 h90
  text "wud" at 34933.2,7625 h90
  text "wud" at 34933.2,7625 h90
  text "zhouxm" at 36033.2,7625 h90
  text "zhouxm" at 36033.2,7625 h90
  text "SHEET 1 OF 1" at 30250,7500 h90
  text "SHEET 1 OF 1" at 30250,7500 h90
  text "8" at 6202.6,6510 h156
  text "8" at 6202.6,6510 h156
  text "7" at 10327.6,6510 h156
  text "7" at 10327.6,6510 h156
  text "6" at 14452.6,6510 h156
  text "6" at 14452.6,6510 h156
  text "5" at 18577.6,6510 h156
  text "5" at 18577.6,6510 h156
  text "4" at 22702.6,6510 h156
  text "4" at 22702.6,6510 h156
  text "3" at 26827.6,6510 h156
  text "3" at 26827.6,6510 h156
  text "2" at 30952.6,6510 h156
  text "2" at 30952.6,6510 h156
  text "1" at 35077.6,6510 h156
  text "1" at 35077.6,6510 h156
OUTLINE:
  circle w1: c17826.06,13771.87 r155
  circle w1: c17826.06,19756.13 r155
  circle w1: c17826.06,15189.2 r155
  circle w1: c17739.45,16252.19 r155
  circle w1: c17739.45,17275.81 r155
  circle w1: c17826.06,18338.8 r155
  lines w1: 8245.15,12237.15 24386.88,12237.15 24386.88,21292.27 8245.15,21292.27 8245.15,12237.15 ; 16822.76,13595.28 ccw(c16836.9,13581.14) 16851.04,13567 16985.15,13701.11 16985.15,13842.63 16885.15,13942.63 16885.15,14057.89 ccw(c16865.15,14057.89) 16845.15,14057.89 16845.15,13926.07 16945.15,13826.07 16945.15,13717.67 16822.76,13595.28 ; 16822.76,15012.61 ccw(c16836.9,14998.47) 16851.04,14984.33 16985.15,15118.44 16985.15,15259.96 16885.15,15359.96 16885.15,15475.22 ccw(c16865.15,15475.22) 16845.15,15475.22 16845.15,15343.4 16945.15,15243.4 16945.15,15135 16822.76,15012.61 ; 16822.76,18162.21 ccw(c16836.9,18148.07) 16851.04,18133.93 16985.15,18268.04 16985.15,18409.56 16885.15,18509.56 16885.15,18624.82 ccw(c16865.15,18624.82) 16845.15,18624.82 16845.15,18493 16945.15,18393 16945.15,18284.6 16822.76,18162.21 ; 16822.76,19579.54 ccw(c16836.9,19565.4) 16851.04,19551.26 16985.15,19685.37 16985.15,19826.89 16885.15,19926.89 16885.15,20042.15 ccw(c16865.15,20042.15) 16845.15,20042.15 16845.15,19910.33 16945.15,19810.33 16945.15,19701.93 16822.76,19579.54
DRAWING_ORIGIN:
  lines w1: 8220.15,12237.15 8270.15,12237.15 ; 8245.15,12212.15 8245.15,12262.15
PIN_NUMBER:
  text "1" at 8395.83,21134.79 h17
  text "1" at 15582.6,21134.79 h17
  text "1" at 24222.6,21134.79 h17
  text "1" at 8690,20845 h50
  text "1" at 23855,12775 h50
  text "1" at 8690,12690 h50
  text "1" at 8395.83,12394.63 h17
  text "1" at 24222.6,12394.63 h17
PLACE_BOUND_TOP:
  lines w1: 8294.36,12286.36 8510.9,12286.36 ; 8294.36,12286.36 8294.36,12502.9 ; 8294.36,12286.36 8510.9,12286.36 ; 8294.36,12286.36 8294.36,12502.9 ; 8294.36,12502.9 8510.9,12502.9 ; 8294.36,12502.9 8510.9,12502.9 ; 8294.36,21026.52 8510.9,21026.52 ; 8294.36,21026.52 8294.36,21243.06 ; 8294.36,21026.52 8510.9,21026.52 ; 8294.36,21026.52 8294.36,21243.06 ; 8294.36,21243.06 8510.9,21243.06 ; 8294.36,21243.06 8510.9,21243.06 ; 8510.9,12286.36 8510.9,12502.9 ; 8510.9,12286.36 8510.9,12502.9 ; 8510.9,21026.52 8510.9,21243.06 ; 8510.9,21026.52 8510.9,21243.06 ; 15481.13,21026.52 15697.67,21026.52 ; 15481.13,21026.52 15481.13,21243.06 ; 15481.13,21026.52 15697.67,21026.52 ; 15481.13,21026.52 15481.13,21243.06 ; 15481.13,21243.06 15697.67,21243.06 ; 15481.13,21243.06 15697.67,21243.06 ; 15697.67,21026.52 15697.67,21243.06 ; 15697.67,21026.52 15697.67,21243.06 ; 24121.13,12286.36 24337.67,12286.36 ; 24121.13,12286.36 24121.13,12502.9 ; 24121.13,12286.36 24337.67,12286.36 ; 24121.13,12286.36 24121.13,12502.9 ; 24121.13,12502.9 24337.67,12502.9 ; 24121.13,12502.9 24337.67,12502.9 ; 24121.13,21026.52 24337.67,21026.52 ; 24121.13,21026.52 24121.13,21243.06 ; 24121.13,21026.52 24337.67,21026.52 ; 24121.13,21026.52 24121.13,21243.06 ; 24121.13,21243.06 24337.67,21243.06 ; 24121.13,21243.06 24337.67,21243.06 ; 24337.67,12286.36 24337.67,12502.9 ; 24337.67,12286.36 24337.67,12502.9 ; 24337.67,21026.52 24337.67,21243.06 ; 24337.67,21026.52 24337.67,21243.06
ASSEMBLY_TOP:
  text "REF/ASSEMBLY" at 8498.2,21469.44 h17
  text "REF*" at 15739.37,21469.44 h17
  text "REF/ASSEMBLY" at 24324.97,21469.44 h17
  text "DEV/ASSEMBLY" at 8498.2,21430.07 h17
  text "DEV/ASSEMBLY" at 15684.97,21430.07 h17
  text "DEV/ASSEMBLY" at 24324.97,21430.07 h17
  text "VAL/ASSEMBLY" at 8498.2,21390.7 h17
  text "VAL/ASSEMBLY" at 15684.97,21390.7 h17
  text "VAL/ASSEMBLY" at 24324.97,21390.7 h17
  text "REF/ASSEMBLY" at 8498.2,12729.28 h17
  text "REF/ASSEMBLY" at 24324.97,12729.28 h17
  text "DEV/ASSEMBLY" at 8498.2,12689.91 h17
  text "DEV/ASSEMBLY" at 24324.97,12689.91 h17
  text "VAL/ASSEMBLY" at 8498.2,12650.54 h17
  text "VAL/ASSEMBLY" at 24324.97,12650.54 h17
PLACE_BOUND_BOTTOM:
  lines w1: 8690,12670 8730,12670 8730,12710 8690,12710 8690,12670 ; 8690,20825 8730,20825 8730,20865 8690,20865 8690,20825 ; 23855,12755 23895,12755 23895,12795 23855,12795 23855,12755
